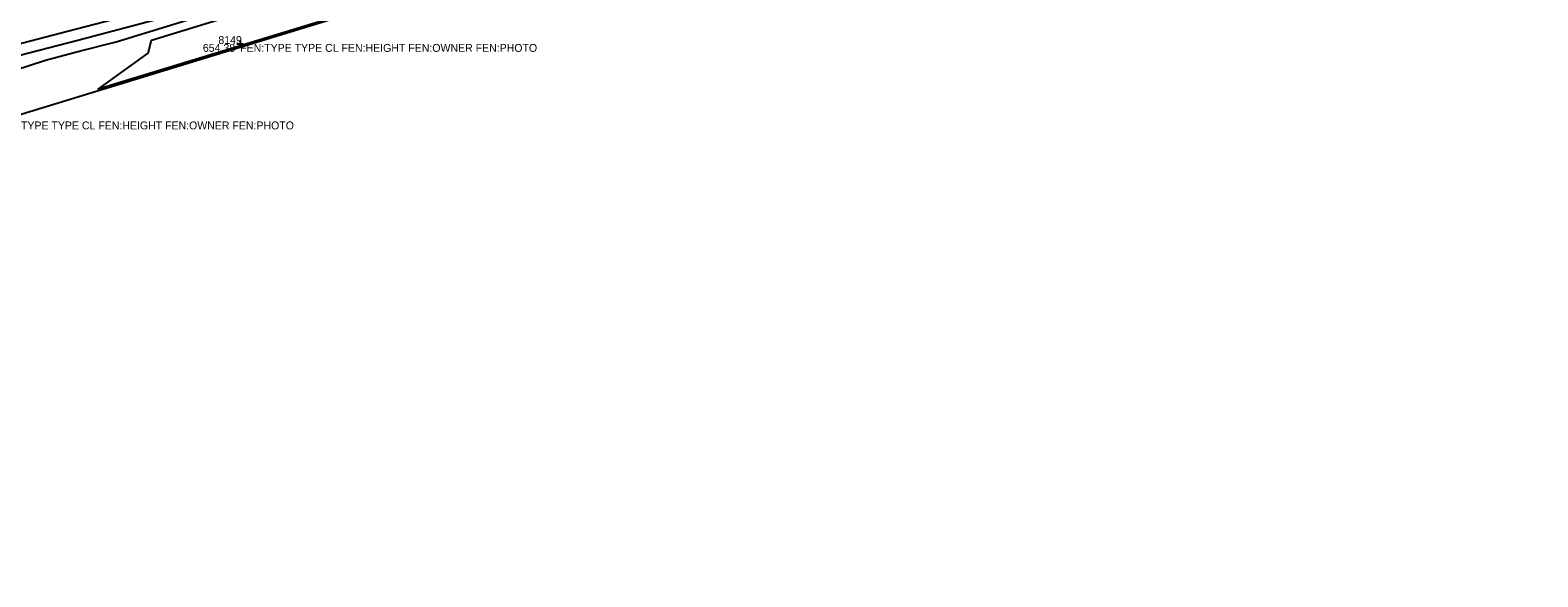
# Model space of a CAD drawing. Extents: x 2129350 to 2137777, y 657588 to 659885.
# Drawn here: x 2135283.8 to 2135513.3, y 659106.1 to 659189.3 of the extents above; entities that cross this region are included whole.
import ezdxf

# ---------------------------------------------------------------- set-up
doc = ezdxf.new("R2010")
doc.units = 0
for name, color, linetype in [('DT_X_Contour_Minor', 7, 'Continuous'), ('DT_X_TIN_Hull', 7, 'Continuous'), ('SV_X_Shot_Marker', 7, 'Continuous'), ('SV_X_Text_Comment', 7, 'Continuous'), ('SV_X_Text_Elevation', 7, 'Continuous'), ('SV_X_Text_Name', 7, 'Continuous')]:
    doc.layers.add(name, color=color, linetype=linetype)

msp = doc.modelspace()

# ---------------------------------------------------------------- linework, layer by layer
at = {"layer": 'DT_X_Contour_Minor'}
for points in [[(2135271.93, 659184.59), (2135290.87, 659189.52), (2135311.4, 659194.87), (2135313.53, 659195.53), (2135315.3, 659195.94), (2135337.22, 659201.72), (2135340.35, 659202.42), (2135358.37, 659207.17), (2135359.01, 659207.38), (2135378.45, 659213.14), (2135383.05, 659214.67), (2135401.97, 659220.32), (2135407.04, 659221.98), (2135410.71, 659223.08), (2135416.29, 659224.39), (2135434.69, 659228.83), (2135442.84, 659230.75), (2135458.51, 659234.52), (2135467.54, 659236.53), (2135482.71, 659240.39), (2135490.94, 659242.21), (2135505.72, 659246.01), (2135506.33, 659246.18), (2135521.05, 659249.65)], [(2135315.37, 659191.78), (2135324.82, 659193.97), (2135325.41, 659192.08), (2135345.79, 659196.09), (2135294.15, 659180.31), (2135301.8, 659185.83), (2135302.31, 659187.78), (2135315.37, 659191.78)], [(2135267.29, 659178.62), (2135286.13, 659184.75), (2135291.29, 659186.09), (2135296.89, 659187.55), (2135314.76, 659193.03)], [(2135279.03, 659184.67), (2135291.08, 659187.81), (2135304.14, 659191.21)]]:
    msp.add_lwpolyline(points, dxfattribs=at)
at = {"layer": 'DT_X_TIN_Hull'}
msp.add_lwpolyline([(2134339.8, 658900.97), (2134383.27, 658929.14), (2134438.63, 658944.81), (2134484.26, 658949.93), (2134535.84, 658964.93), (2134589.33, 658980.68), (2134684.69, 659007.18), (2134781.08, 659033.65), (2134834.81, 659047.4), (2134874.97, 659059.96), (2134937.76, 659078.48), (2134974.62, 659089.26), (2135069.17, 659114.77), (2135119.62, 659129.04), (2135174.31, 659143.84), (2135216.92, 659155.82), (2135278.77, 659175.41), (2135358.06, 659199.71), (2135416.07, 659215.59), (2135505.42, 659239.1), (2135573.46, 659256.02)], dxfattribs=at)
at = {"layer": 'SV_X_Shot_Marker'}
for p, q in [((2135315.29, 659187.21), (2135316.29, 659187.21)), ((2135315.79, 659187.71), (2135315.79, 659186.71)), ((2135315.79, 659187.21), (2135315.79, 659187.21))]:
    msp.add_line(p, q, dxfattribs=at)

# ---------------------------------------------------------------- texts
at = {"layer": 'SV_X_Text_Comment'}
for p in [(2135315.79, 659186.01), (2135278.77, 659174.21)]:
    msp.add_text('FEN:TYPE TYPE CL FEN:HEIGHT FEN:OWNER FEN:PHOTO', height=1.2, dxfattribs=at).set_placement(p)
at = {"layer": 'SV_X_Text_Elevation'}
msp.add_text('654.38', height=1.2, dxfattribs=at).set_placement((2135310.11, 659186.01))
at = {"layer": 'SV_X_Text_Name'}
msp.add_text('8149', height=1.2, dxfattribs=at).set_placement((2135312.47, 659187.21))

doc.saveas('drawing.dxf')
